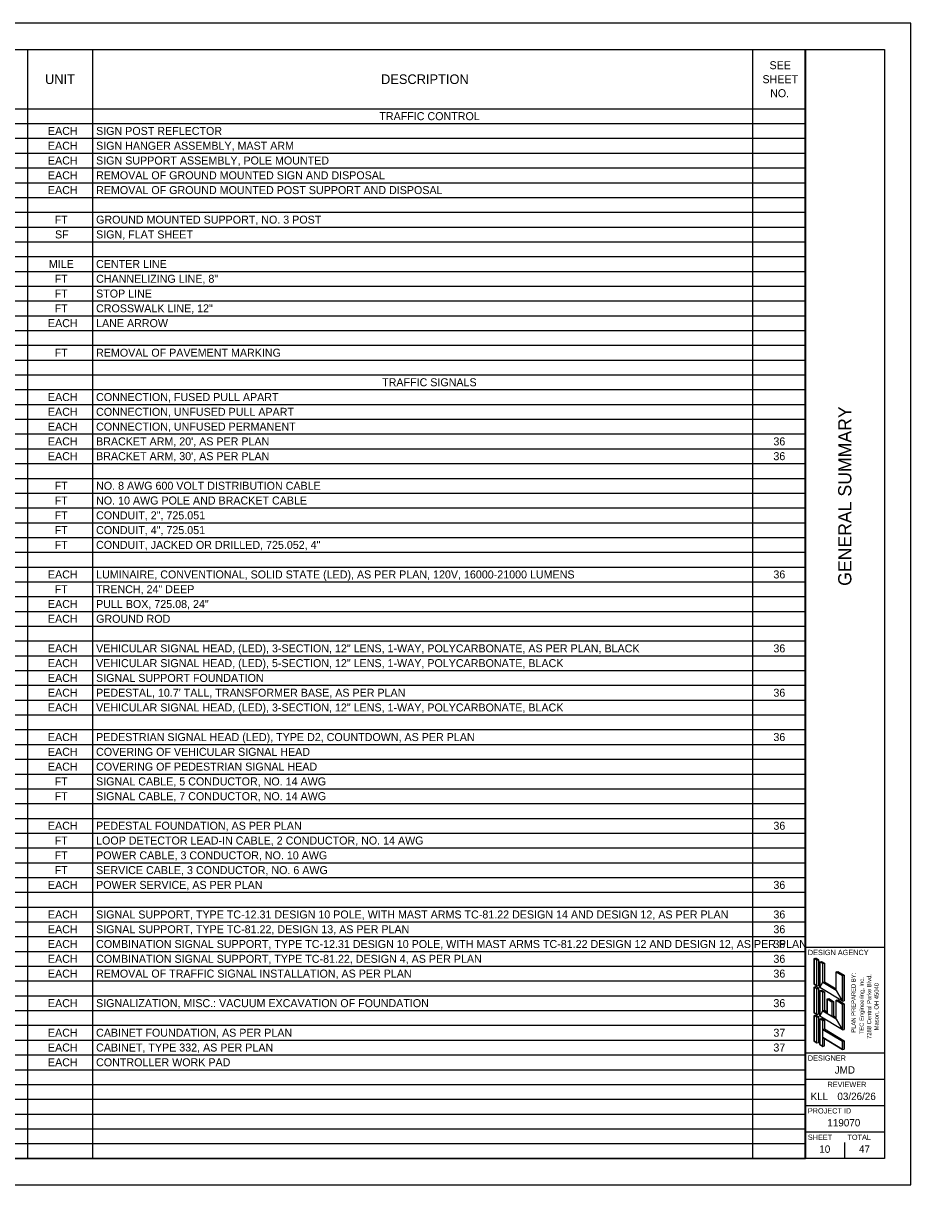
# Model space of a CAD drawing. Extents: x 0 to 34, y 0 to 22.
# Drawn here: x 17.18 to 34, y 0 to 22 of the extents above; entities that cross this region are included whole.
import ezdxf

# ---------------------------------------------------------------- set-up
doc = ezdxf.new("R2010")
doc.units = 0
for name, color, linetype in [('Default', 7, 'Continuous'), ('SH_Border', 7, 'Continuous'), ('SH_Cut_Line', 7, 'Continuous'), ('SH_Data', 7, 'Continuous'), ('SH_Text', 7, 'Continuous')]:
    doc.layers.add(name, color=color, linetype=linetype)

msp = doc.modelspace()

# ---------------------------------------------------------------- linework, layer by layer
at = {"layer": 'Default'}
for p, q in [((1.5, 21.5), (32.004, 21.5)), ((17.262, 21.5), (17.262, 0.5)), ((18.498, 21.5), (18.498, 0.5)), ((30.999, 21.5), (30.999, 0.5)), ((32.004, 21.5), (32.004, 0.5)), ((1.5, 20.38), (32.004, 20.38)), ((1.5, 20.1), (32.004, 20.1)), ((1.5, 19.82), (32.004, 19.82)), ((1.5, 19.54), (32.004, 19.54)), ((1.5, 19.26), (32.004, 19.26)), ((1.5, 18.98), (32.004, 18.98)), ((1.5, 18.7), (32.004, 18.7)), ((1.5, 18.42), (32.004, 18.42)), ((1.5, 18.14), (32.004, 18.14)), ((1.5, 17.86), (32.004, 17.86)), ((1.5, 17.58), (32.004, 17.58)), ((1.5, 17.3), (32.004, 17.3)), ((1.5, 17.02), (32.004, 17.02)), ((1.5, 16.74), (32.004, 16.74)), ((1.5, 16.46), (32.004, 16.46)), ((1.5, 16.18), (32.004, 16.18)), ((1.5, 15.9), (32.004, 15.9)), ((1.5, 15.62), (32.004, 15.62)), ((1.5, 15.34), (32.004, 15.34)), ((1.5, 15.06), (32.004, 15.06)), ((1.5, 14.78), (32.004, 14.78)), ((1.5, 14.5), (32.004, 14.5)), ((1.5, 14.22), (32.004, 14.22)), ((1.5, 13.94), (32.004, 13.94)), ((1.5, 13.66), (32.004, 13.66)), ((1.5, 13.38), (32.004, 13.38)), ((1.5, 13.1), (32.004, 13.1)), ((1.5, 12.82), (32.004, 12.82)), ((1.5, 12.54), (32.004, 12.54)), ((1.5, 12.26), (32.004, 12.26)), ((1.5, 11.98), (32.004, 11.98)), ((1.5, 11.7), (32.004, 11.7)), ((1.5, 11.42), (32.004, 11.42)), ((1.5, 11.14), (32.004, 11.14)), ((1.5, 10.86), (32.004, 10.86)), ((1.5, 10.58), (32.004, 10.58)), ((1.5, 10.3), (32.004, 10.3)), ((1.5, 10.02), (32.004, 10.02)), ((1.5, 9.74), (32.004, 9.74)), ((1.5, 9.46), (32.004, 9.46)), ((1.5, 9.18), (32.004, 9.18)), ((1.5, 8.9), (32.004, 8.9)), ((1.5, 8.62), (32.004, 8.62)), ((1.5, 8.34), (32.004, 8.34)), ((1.5, 8.06), (32.004, 8.06)), ((1.5, 7.78), (32.004, 7.78)), ((1.5, 7.5), (32.004, 7.5)), ((1.5, 7.22), (32.004, 7.22)), ((1.5, 6.94), (32.004, 6.94)), ((1.5, 6.66), (32.004, 6.66)), ((1.5, 6.38), (32.004, 6.38)), ((1.5, 6.1), (32.004, 6.1)), ((1.5, 5.82), (32.004, 5.82)), ((1.5, 5.54), (32.004, 5.54)), ((1.5, 5.26), (32.004, 5.26)), ((1.5, 4.98), (32.004, 4.98)), ((1.5, 4.7), (32.004, 4.7)), ((1.5, 4.42), (32.004, 4.42)), ((1.5, 4.14), (32.004, 4.14)), ((1.5, 3.86), (32.004, 3.86)), ((1.5, 3.58), (32.004, 3.58)), ((1.5, 3.3), (32.004, 3.3)), ((1.5, 3.02), (32.004, 3.02)), ((1.5, 2.74), (32.004, 2.74)), ((1.5, 2.46), (32.004, 2.46)), ((1.5, 2.18), (32.004, 2.18)), ((1.5, 1.9), (32.004, 1.9)), ((1.5, 1.62), (32.004, 1.62)), ((1.5, 1.34), (32.004, 1.34)), ((1.5, 1.06), (32.004, 1.06)), ((1.5, 0.78), (32.004, 0.78)), ((1.5, 0.5), (32.004, 0.5))]:
    msp.add_line(p, q, dxfattribs=at)
at = {"layer": 'SH_Border'}
for p, q in [((32, 0.5), (32, 21.5)), ((32, 4.5), (33.5, 4.5)), ((32, 2.5), (33.5, 2.5)), ((32, 2), (33.5, 2)), ((32, 1.5), (33.5, 1.5)), ((32, 1), (33.5, 1))]:
    msp.add_line(p, q, dxfattribs=at)
msp.add_lwpolyline([(1.5, 21.5), (33.5, 21.5), (33.5, 0.5), (1.5, 0.5)], close=True, dxfattribs=at)
at = {"layer": 'SH_Cut_Line'}
msp.add_lwpolyline([(0, 0), (34, 0), (34, 22), (0, 22)], close=True, dxfattribs=at)
at = {"layer": 'SH_Data'}
for p, q in [((32.75, 3.5), (32.75, 3.5)), ((32.375, 0.675), (32.375, 0.675)), ((32.75, 0.5), (32.75, 0.8))]:
    msp.add_line(p, q, dxfattribs=at)
at = {"layer": 'SH_Text'}
for p, q in [((32.169, 4.285), (32.201, 4.294)), ((32.169, 3.799), (32.169, 4.285)), ((32.223, 4.253), (32.169, 4.285)), ((32.255, 4.261), (32.201, 4.294)), ((32.223, 4.253), (32.255, 4.261)), ((32.223, 3.767), (32.223, 4.253)), ((32.255, 3.775), (32.255, 4.261)), ((32.277, 4.221), (32.309, 4.229)), ((32.331, 4.188), (32.277, 4.221)), ((32.277, 3.735), (32.277, 4.221)), ((32.309, 4.229), (32.363, 4.196)), ((32.331, 4.188), (32.363, 4.196)), ((32.331, 3.837), (32.331, 4.188)), ((32.363, 4.196), (32.363, 3.845)), ((32.587, 4.034), (32.62, 4.042)), ((32.587, 3.683), (32.587, 4.034)), ((32.709, 3.961), (32.587, 4.034)), ((32.62, 4.042), (32.741, 3.97)), ((32.709, 3.961), (32.741, 3.97)), ((32.709, 3.475), (32.709, 3.961)), ((32.741, 3.97), (32.741, 3.484)), ((32.223, 3.767), (32.169, 3.799)), ((32.169, 3.745), (32.201, 3.754)), ((32.169, 3.259), (32.169, 3.745)), ((32.223, 3.713), (32.169, 3.745)), ((32.255, 3.722), (32.201, 3.754)), ((32.223, 3.767), (32.255, 3.775)), ((32.331, 3.837), (32.363, 3.845)), ((32.587, 3.683), (32.331, 3.837)), ((32.363, 3.845), (32.587, 3.711)), ((32.223, 3.713), (32.255, 3.722)), ((32.223, 3.227), (32.223, 3.713)), ((32.255, 3.236), (32.255, 3.722)), ((32.709, 3.475), (32.277, 3.735)), ((32.277, 3.681), (32.309, 3.689)), ((32.277, 3.195), (32.277, 3.681)), ((32.331, 3.648), (32.277, 3.681)), ((32.309, 3.689), (32.363, 3.656)), ((32.331, 3.648), (32.363, 3.656)), ((32.331, 3.297), (32.331, 3.648)), ((32.363, 3.656), (32.363, 3.305)), ((32.415, 3.519), (32.448, 3.527)), ((32.448, 3.527), (32.535, 3.474)), ((32.331, 3.297), (32.363, 3.305)), ((32.363, 3.305), (32.415, 3.274)), ((32.415, 3.519), (32.415, 3.247)), ((32.415, 3.519), (32.503, 3.466)), ((32.503, 3.466), (32.535, 3.474)), ((32.503, 3.466), (32.503, 3.194)), ((32.535, 3.474), (32.535, 3.202)), ((32.587, 3.494), (32.62, 3.502)), ((32.587, 3.143), (32.587, 3.494)), ((32.709, 3.421), (32.587, 3.494)), ((32.62, 3.502), (32.741, 3.43)), ((32.709, 3.475), (32.741, 3.484)), ((32.709, 3.421), (32.741, 3.43)), ((32.709, 2.935), (32.709, 3.421)), ((32.741, 3.43), (32.741, 2.944)), ((32.223, 3.227), (32.169, 3.259)), ((32.169, 3.205), (32.201, 3.215)), ((32.169, 2.719), (32.169, 3.205)), ((32.223, 3.173), (32.169, 3.205)), ((32.255, 3.181), (32.201, 3.215)), ((32.222, 3.173), (32.255, 3.181)), ((32.223, 3.227), (32.255, 3.236)), ((32.223, 2.687), (32.223, 3.173)), ((32.255, 2.695), (32.255, 3.181)), ((32.709, 2.935), (32.277, 3.195)), ((32.277, 3.141), (32.309, 3.151)), ((32.331, 3.108), (32.277, 3.141)), ((32.277, 2.655), (32.277, 3.141)), ((32.309, 3.151), (32.363, 3.116)), ((32.415, 3.247), (32.331, 3.297)), ((32.331, 3.108), (32.363, 3.116)), ((32.331, 2.944), (32.331, 3.108)), ((32.363, 3.116), (32.363, 2.952)), ((32.503, 3.194), (32.535, 3.202)), ((32.587, 3.143), (32.503, 3.194)), ((32.535, 3.202), (32.587, 3.171)), ((32.331, 2.944), (32.363, 2.952)), ((32.331, 2.944), (32.709, 2.717)), ((32.363, 2.952), (32.741, 2.725)), ((32.709, 2.935), (32.741, 2.944)), ((32.223, 2.687), (32.169, 2.719)), ((32.223, 2.687), (32.255, 2.695)), ((32.331, 2.622), (32.277, 2.655)), ((32.331, 2.787), (32.709, 2.56)), ((32.331, 2.622), (32.331, 2.787)), ((32.363, 2.63), (32.363, 2.767)), ((32.709, 2.717), (32.741, 2.725)), ((32.709, 2.56), (32.709, 2.717)), ((32.741, 2.725), (32.741, 2.568)), ((32.331, 2.622), (32.363, 2.63)), ((32.709, 2.56), (32.741, 2.568))]:
    msp.add_line(p, q, dxfattribs=at)
for points in [[(32.169, 3.799), (32.223, 3.767), (32.223, 4.253), (32.169, 4.285)], [(32.277, 3.735), (32.331, 3.837), (32.331, 4.188), (32.277, 4.221)], [(32.709, 3.475), (32.587, 3.683), (32.587, 4.034), (32.709, 3.961)], [(32.169, 3.259), (32.223, 3.227), (32.223, 3.713), (32.169, 3.745)], [(32.277, 3.735), (32.331, 3.837), (32.587, 3.683), (32.709, 3.475)], [(32.277, 3.195), (32.331, 3.297), (32.331, 3.648), (32.277, 3.681)], [(32.415, 3.247), (32.415, 3.519), (32.503, 3.466), (32.503, 3.194)], [(32.709, 2.935), (32.587, 3.143), (32.587, 3.494), (32.709, 3.421)], [(32.169, 2.719), (32.223, 2.687), (32.223, 3.173), (32.169, 3.205)], [(32.277, 3.195), (32.331, 3.297), (32.587, 3.143), (32.709, 2.935)], [(32.277, 2.655), (32.331, 2.622), (32.331, 3.108), (32.277, 3.141)], [(32.331, 2.787), (32.331, 2.944), (32.709, 2.717), (32.709, 2.56)]]:
    msp.add_lwpolyline(points, close=True, dxfattribs=at)

# ---------------------------------------------------------------- texts
at = {"layer": 'Default'}
for s, height, p in [('SEE ', 0.1515, (31.324, 21.129)), ('UNIT', 0.1818, (17.597, 20.849)), ('DESCRIPTION', 0.18184, (23.963, 20.849)), ('SHEET ', 0.1515, (31.19, 20.864)), ('NO.', 0.1515, (31.335, 20.599)), ('TRAFFIC CONTROL', 0.15153, (23.931, 20.164)), ('EACH', 0.1515, (17.652, 19.884)), ('SIGN POST REFLECTOR', 0.15153, (18.564, 19.884)), ('EACH', 0.1515, (17.652, 19.604)), ('SIGN HANGER ASSEMBLY, MAST ARM', 0.15153, (18.564, 19.604)), ('EACH', 0.1515, (17.652, 19.324)), ('SIGN SUPPORT ASSEMBLY, POLE MOUNTED', 0.15153, (18.564, 19.324)), ('EACH', 0.1515, (17.652, 19.044)), ('REMOVAL OF GROUND MOUNTED SIGN AND DISPOSAL', 0.15153, (18.564, 19.044)), ('EACH', 0.1515, (17.652, 18.764)), ('REMOVAL OF GROUND MOUNTED POST SUPPORT AND DISPOSAL', 0.15153, (18.564, 18.764)), ('FT', 0.1515, (17.779, 18.204)), ('GROUND MOUNTED SUPPORT, NO. 3 POST', 0.15153, (18.564, 18.204)), ('SF', 0.1515, (17.786, 17.924)), ('SIGN, FLAT SHEET', 0.15153, (18.564, 17.924)), ('MILE', 0.1515, (17.669, 17.364)), ('CENTER LINE', 0.15153, (18.564, 17.364)), ('FT', 0.1515, (17.779, 17.084)), ('CHANNELIZING LINE, 8"', 0.15153, (18.564, 17.084)), ('FT', 0.1515, (17.779, 16.804)), ('STOP LINE', 0.1515, (18.564, 16.804)), ('FT', 0.1515, (17.779, 16.524)), ('CROSSWALK LINE, 12"', 0.15153, (18.564, 16.524)), ('EACH', 0.1515, (17.652, 16.244)), ('LANE ARROW', 0.1515, (18.564, 16.244)), ('FT', 0.1515, (17.779, 15.684)), ('REMOVAL OF PAVEMENT MARKING', 0.15153, (18.564, 15.684)), ('TRAFFIC SIGNALS', 0.15153, (23.984, 15.124)), ('EACH', 0.1515, (17.652, 14.844)), ('CONNECTION, FUSED PULL APART', 0.15153, (18.564, 14.844)), ('EACH', 0.1515, (17.652, 14.564)), ('CONNECTION, UNFUSED PULL APART', 0.15153, (18.564, 14.564)), ('EACH', 0.1515, (17.652, 14.284)), ('CONNECTION, UNFUSED PERMANENT', 0.15153, (18.564, 14.284)), ('EACH', 0.1515, (17.652, 14.004)), ("BRACKET ARM, 20', AS PER PLAN", 0.15153, (18.564, 14.004)), ('36', 0.1515, (31.397, 14.004)), ('EACH', 0.1515, (17.652, 13.724)), ("BRACKET ARM, 30', AS PER PLAN", 0.15153, (18.564, 13.724)), ('36', 0.1515, (31.397, 13.724)), ('FT', 0.1515, (17.779, 13.164)), ('NO. 8 AWG 600 VOLT DISTRIBUTION CABLE', 0.15153, (18.564, 13.164)), ('FT', 0.1515, (17.779, 12.884)), ('NO. 10 AWG POLE AND BRACKET CABLE', 0.15153, (18.564, 12.884)), ('FT', 0.1515, (17.779, 12.604)), ('CONDUIT, 2", 725.051', 0.15153, (18.564, 12.604)), ('FT', 0.1515, (17.779, 12.324)), ('CONDUIT, 4", 725.051', 0.15153, (18.564, 12.324)), ('FT', 0.1515, (17.779, 12.044)), ('CONDUIT, JACKED OR DRILLED, 725.052, 4"', 0.15153, (18.564, 12.044)), ('EACH', 0.1515, (17.652, 11.484)), ('LUMINAIRE, CONVENTIONAL, SOLID STATE (LED), AS PER PLAN, 120V, 16000-21000 LUMENS', 0.15153, (18.564, 11.484)), ('36', 0.1515, (31.397, 11.484)), ('FT', 0.1515, (17.779, 11.204)), ('TRENCH, 24" DEEP', 0.15153, (18.564, 11.204)), ('EACH', 0.1515, (17.652, 10.924)), ('PULL BOX, 725.08, 24"', 0.15153, (18.564, 10.924)), ('EACH', 0.1515, (17.652, 10.644)), ('GROUND ROD', 0.1515, (18.564, 10.644)), ('EACH', 0.1515, (17.652, 10.084)), ('VEHICULAR SIGNAL HEAD, (LED), 3-SECTION, 12" LENS, 1-WAY, POLYCARBONATE, AS PER PLAN, BLACK', 0.15153, (18.564, 10.084)), ('36', 0.1515, (31.397, 10.084)), ('EACH', 0.1515, (17.652, 9.804)), ('VEHICULAR SIGNAL HEAD, (LED), 5-SECTION, 12" LENS, 1-WAY, POLYCARBONATE, BLACK', 0.15153, (18.564, 9.804)), ('EACH', 0.1515, (17.652, 9.524)), ('SIGNAL SUPPORT FOUNDATION', 0.15153, (18.564, 9.524)), ('EACH', 0.1515, (17.652, 9.244)), ("PEDESTAL, 10.7' TALL, TRANSFORMER BASE, AS PER PLAN", 0.15153, (18.564, 9.244)), ('36', 0.1515, (31.397, 9.244)), ('EACH', 0.1515, (17.652, 8.964)), ('VEHICULAR SIGNAL HEAD, (LED), 3-SECTION, 12" LENS, 1-WAY, POLYCARBONATE, BLACK', 0.15153, (18.564, 8.964)), ('EACH', 0.1515, (17.652, 8.404)), ('PEDESTRIAN SIGNAL HEAD (LED), TYPE D2, COUNTDOWN, AS PER PLAN', 0.15153, (18.564, 8.404)), ('36', 0.1515, (31.397, 8.404)), ('EACH', 0.1515, (17.652, 8.124)), ('COVERING OF VEHICULAR SIGNAL HEAD', 0.15153, (18.564, 8.124)), ('EACH', 0.1515, (17.652, 7.844)), ('COVERING OF PEDESTRIAN SIGNAL HEAD', 0.15153, (18.564, 7.844)), ('FT', 0.1515, (17.779, 7.564)), ('SIGNAL CABLE, 5 CONDUCTOR, NO. 14 AWG', 0.15153, (18.564, 7.564)), ('FT', 0.1515, (17.779, 7.284)), ('SIGNAL CABLE, 7 CONDUCTOR, NO. 14 AWG', 0.15153, (18.564, 7.284)), ('EACH', 0.1515, (17.652, 6.724)), ('PEDESTAL FOUNDATION, AS PER PLAN', 0.15153, (18.564, 6.724)), ('36', 0.1515, (31.397, 6.724)), ('FT', 0.1515, (17.779, 6.444)), ('LOOP DETECTOR LEAD-IN CABLE, 2 CONDUCTOR, NO. 14 AWG', 0.15153, (18.564, 6.444)), ('FT', 0.1515, (17.779, 6.164)), ('POWER CABLE, 3 CONDUCTOR, NO. 10 AWG', 0.15153, (18.564, 6.164)), ('FT', 0.1515, (17.779, 5.884)), ('SERVICE CABLE, 3 CONDUCTOR, NO. 6 AWG', 0.15153, (18.564, 5.884)), ('EACH', 0.1515, (17.652, 5.604)), ('POWER SERVICE, AS PER PLAN', 0.15153, (18.564, 5.604)), ('36', 0.1515, (31.397, 5.604)), ('EACH', 0.1515, (17.652, 5.044)), ('SIGNAL SUPPORT, TYPE TC-12.31 DESIGN 10 POLE, WITH MAST ARMS TC-81.22 DESIGN 14 AND DESIGN 12, AS PER PLAN', 0.151529, (18.564, 5.044)), ('36', 0.1515, (31.397, 5.044)), ('EACH', 0.1515, (17.652, 4.764)), ('SIGNAL SUPPORT, TYPE TC-81.22, DESIGN 13, AS PER PLAN', 0.15153, (18.564, 4.764)), ('36', 0.1515, (31.397, 4.764)), ('EACH', 0.1515, (17.652, 4.484)), ('COMBINATION SIGNAL SUPPORT, TYPE TC-12.31 DESIGN 10 POLE, WITH MAST ARMS TC-81.22 DESIGN 12 AND DESIGN 12, AS PER PLAN', 0.151529, (18.564, 4.484)), ('36', 0.1515, (31.397, 4.484)), ('EACH', 0.1515, (17.652, 4.204)), ('COMBINATION SIGNAL SUPPORT, TYPE TC-81.22, DESIGN 4, AS PER PLAN', 0.15153, (18.564, 4.204)), ('36', 0.1515, (31.397, 4.204)), ('EACH', 0.1515, (17.652, 3.924)), ('REMOVAL OF TRAFFIC SIGNAL INSTALLATION, AS PER PLAN', 0.15153, (18.564, 3.924)), ('36', 0.1515, (31.397, 3.924)), ('EACH', 0.1515, (17.652, 3.364)), ('SIGNALIZATION, MISC.: VACUUM EXCAVATION OF FOUNDATION', 0.15153, (18.564, 3.364)), ('36', 0.1515, (31.397, 3.364)), ('EACH', 0.1515, (17.652, 2.804)), ('CABINET FOUNDATION, AS PER PLAN', 0.15153, (18.564, 2.804)), ('37', 0.1515, (31.397, 2.804)), ('EACH', 0.1515, (17.652, 2.524)), ('CABINET, TYPE 332, AS PER PLAN', 0.15153, (18.564, 2.524)), ('37', 0.1515, (31.397, 2.524)), ('EACH', 0.1515, (17.652, 2.244)), ('CONTROLLER WORK PAD', 0.15153, (18.564, 2.244))]:
    msp.add_text(s, height=height, dxfattribs=at).set_placement(p)
for s, p in [('PLAN PREPARED BY:', (32.954, 2.88)), ('TEC Engineering, Inc.', (33.11, 2.851)), ('7288 Central Parke Blvd.', (33.25, 2.762)), ('Mason, OH 45040', (33.39, 2.925))]:
    msp.add_text(s, height=0.08, rotation=90, dxfattribs=at).set_placement(p)
at = {"layer": 'SH_Data'}
msp.add_text('GENERAL SUMMARY', height=0.25, rotation=90, dxfattribs=at).set_placement((32.875, 11.344))
for s, height, p in [('DESIGN AGENCY', 0.1, (32.05, 4.35)), ('DESIGNER', 0.1, (32.05, 2.35)), ('JMD', 0.14, (32.558, 2.105)), ('REVIEWER', 0.1, (32.422, 1.85)), ('KLL', 0.14, (32.101, 1.605)), ('03/26/26', 0.14, (32.609, 1.605)), ('PROJECT ID', 0.1, (32.05, 1.35)), ('119070', 0.14, (32.419, 1.105)), ('SHEET', 0.1, (32.05, 0.85)), ('TOTAL', 0.1, (32.8, 0.85)), ('10', 0.14, (32.267, 0.605)), ('47', 0.14, (33.018, 0.605))]:
    msp.add_text(s, height=height, dxfattribs=at).set_placement(p)

doc.saveas('drawing.dxf')
